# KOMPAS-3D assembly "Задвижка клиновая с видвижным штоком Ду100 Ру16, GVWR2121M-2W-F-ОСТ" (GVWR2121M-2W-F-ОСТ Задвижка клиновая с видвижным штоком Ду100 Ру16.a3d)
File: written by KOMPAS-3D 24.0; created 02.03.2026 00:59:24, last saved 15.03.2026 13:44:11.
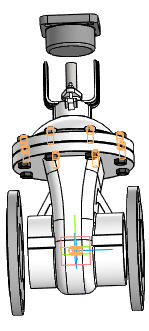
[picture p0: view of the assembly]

Document properties: Автор: R2D2; Полное имя файла: E:\Работа\Зайцев\GVWR2121M-2W-F-ОСТ Задвижка клиновая с видвижным штоком Ду50-300 Ру16\DN100\Исходные материалы\GVWR2121M-2W-F-ОСТ Задвижка клиновая с видвижным штоком Ду100 Ру16.a3d

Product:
- Component [detail]: ANSI B18.2.4.2M - M5x0,8 - 8  | designation ANSI B18.2.4.2M - M5x0,8  | qty 2  | pos. 2  | Масса: 0.00167; Комментарий: Типы метрических   шестигранных гаек   2; Автор: R2D2; additional columns: Сталь, мягкая; source file: ANSI B18.2.4.2M - M5x0,8 ANSI B18.2.4.2M - M5x0,8 - 8.m3d
- Component [detail]: Деталь1  | qty 1  | pos. 3  | Масса: 36.799325; additional columns: Типовые; source file: 2.m3d
- Component [detail]: Фланец  | qty 2  | pos. 3  | Масса: 3.822467; Автор: R2D2; additional columns: Типовые; source file: Фланец DN100 PN16 b20.m3d
- Component [standard]: Болт М12-6gx50.88.45Г.019 ГОСТ 7798-70  | qty 8  | Материал: Сталь 45Г (density 7850 kg/m3); Масса: 0.06053; Раздел спецификации: Стандартные изделия; Рассекать на разрезах: no; additional columns: BOSimple***Material:39848d99-529e-4aa2-825c-393daa009d15
- Component [standard]: Гайка М12-6H ГОСТ 5915-70  | qty 24  | Масса: 0.0184; Раздел спецификации: Стандартные изделия; Рассекать на разрезах: no
- Component [assembly]: DN50_3D_STEP  | designation Сборка  | qty 1  | pos. 4  | Масса: 2.725126; Автор: R2D2; source file: Фланец А.a3d
- Part/product: Задвижка клиновая с видвижным штоком Ду100 Ру16  | designation GVWR2121M-2W-F-ОСТ
    Масса: 31
    Раздел спецификации: Прочие изделия
    Примечание: D040-08601

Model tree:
1. Массив по концентрической сетке:1  (labels: Грань.Твердое тело1)  (8 pattern instances)
     Шаг 2 = 360
2. Массив по концентрической сетке:2  (with: Грань.Элемент вращения:1, Грань.Операция без истории:2)  (labels: Грань.Твердое тело1; Грань.Solid1)  (2 pattern instances)
     Шаг 2 = 360; Расстояние = -115; Ориентация = 2; Расстояние = -415

Referenced files in E:\Работа\Зайцев\GVWR2121M-2W-F-ОСТ Задвижка клиновая с видвижным штоком Ду50-300 Ру16\DN100\Исходные материалы\: ANSI B18.2.4.2M - M5x0,8 ANSI B18.2.4.2M - M5x0,8 - 8.m3d, 2.m3d, Фланец DN100 PN16 b20.m3d, Фланец А.a3d
Referenced files in E:\Работа\Зайцев\GVWR2626M-2W-F-S Задвижка клиновая с выдвижным штоком DN.ru Ду50-300 Ру16\DN100\исходные материалы\: 1.m3d, Фланец DN100 PN16 b20.m3d
Referenced files in C:\Program Files\ASCON\KOMPAS-3D v24\Libs\PolynomLib\DATA\vault\Methods\Kompas\3D\: PLib_Bolt_1_900.m3d, PLib_Nut_OST92_900.m3d
Referenced files in E:\Работа\Зайцев\GVWR3131M-2W-F-S Задвижка клиновая с выдвижным штоком DN.ru Ду50-200 Ру63\DN100\исходные материалы\: ANSI B18.2.4.2M - M5x0,8 ANSI B18.2.4.2M - M5x0,8 - 8.m3d
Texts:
  ANSI B18.2.4.2M - M5x0,8
  Крепежное изделие ГОСТ
  BOSimple***PART:25ccc031-f2ed-a43b-e633-090566d53ffa***SHORTLOC:Root±30±20±10±80±10±©{}30±©{BASE}130±290[9;Цинковое, хроматированное;Сталь 45Г ГОСТ 4543-2016;50;12;19;1,75;8.8]
  BOSimple***Material:39848d99-529e-4aa2-825c-393daa009d15
  BOSimple***PART:dfaf85ed-3e43-003f-b29c-9c5b054070d3***SHORTLOC:Root±30±10±20±©{}110±10±50±60[Нет;Без покрытия;Без указания материала;-;12;1,75;19]
  Программные изделия  и базы данных
  GVWR2121M-2W-F-ОСТ
  ANSI B18.2.4.2M - M5x0,8 ANSI B18.2.4.2M - M5x0,8 - 8 (1)
  Деталь1 Деталь1
  Фланец (1)
  Фланец (2)
  Болт М12-6gx50.88.45Г.019 ГОСТ 7798-70 (1)
  hole1
  hole2
  Гайка М12-6H ГОСТ 5915-70 (1)
  bcut1
  hcut1
  cut1
  Гайка М12-6H ГОСТ 5915-70 (2)
  Гайка М12-6H ГОСТ 5915-70 (3)
  Сборка DN50_3D_STEP
  Ось Z.Начало координат
  Ось Y.Начало координат
  Плоскость ZX.Начало координат
  Плоскость XY.Начало координат
  Plane. Начало координат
